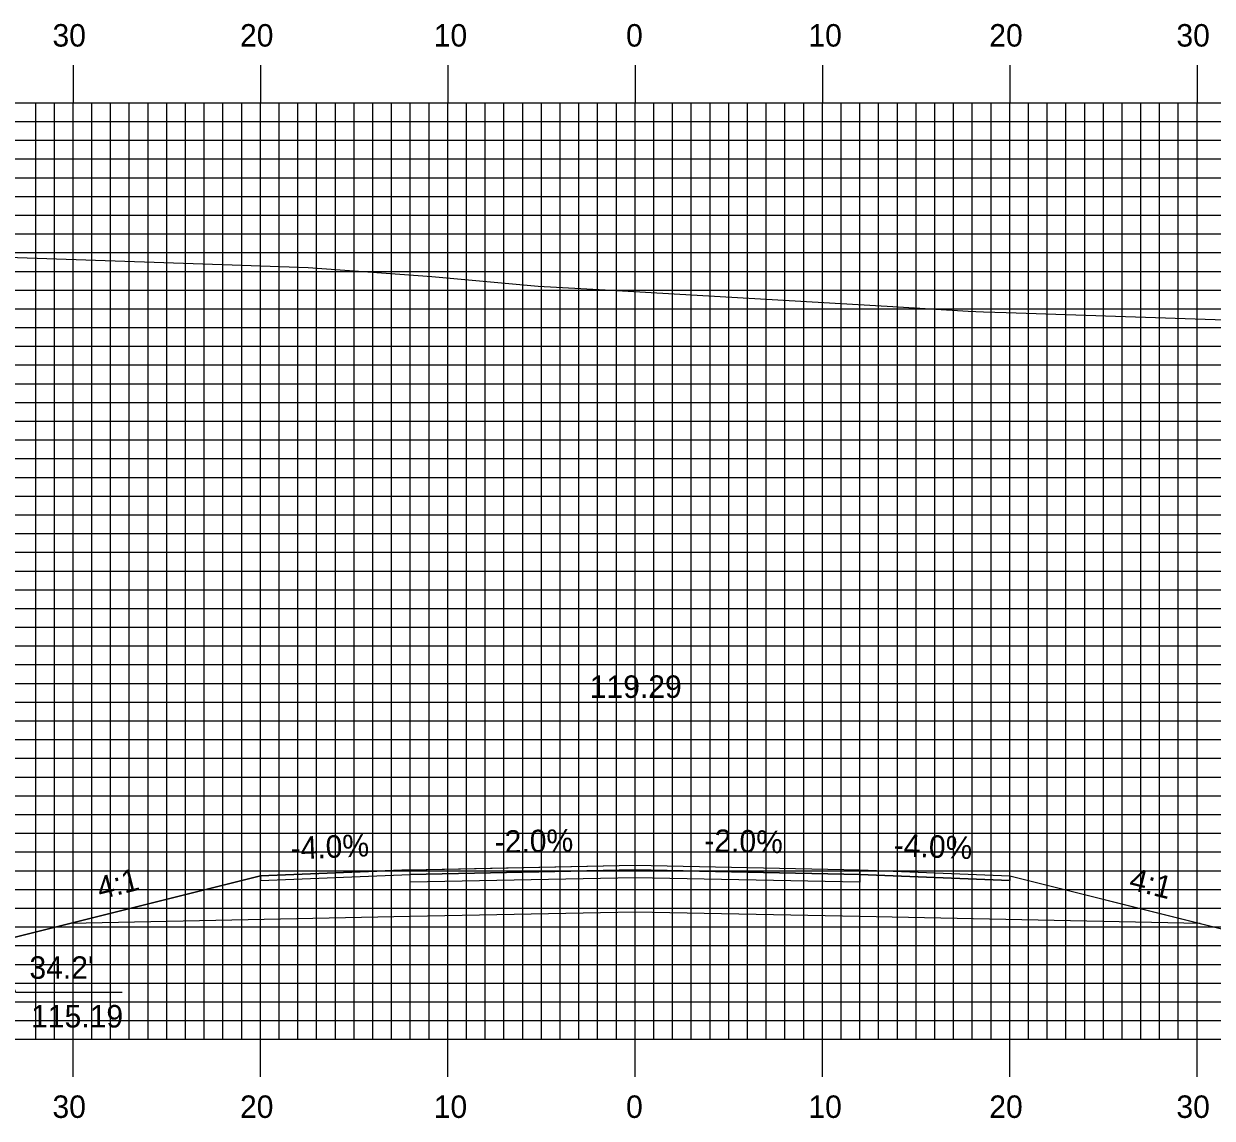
# Model space of a CAD drawing. Extents: x 1770055 to 1770398, y 442591 to 442811.
# Drawn here: x 1770187.9 to 1770251.3, y 442679.4 to 442737.9 of the extents above; entities that cross this region are included whole.
import ezdxf

# ---------------------------------------------------------------- set-up
doc = ezdxf.new("R2010")
doc.units = 0
for name, color, linetype in [('ANNOTATION', 7, 'Continuous'), ('D_Roadway_Centerline', 7, 'Continuous'), ('D_Roadway_Centerline_Text', 7, 'Continuous'), ('D_Roadway_Edge_Shoulder', 7, 'Continuous'), ('D_Roadway_Edge_TW', 7, 'Continuous'), ('D_Roadway_Pavement', 7, 'Continuous'), ('D_Roadway_SlopeLines', 7, 'Continuous'), ('D_Roadway_SubGrade', 7, 'Continuous'), ('H_V ANNOTATION', 7, 'Continuous'), ('MAJOR', 7, 'Continuous'), ('MINOR', 7, 'Continuous'), ('S_Roadway_Centerline', 7, 'Continuous')]:
    doc.layers.add(name, color=color, linetype=linetype)

msp = doc.modelspace()

# ---------------------------------------------------------------- linework, layer by layer
at = {"layer": 'ANNOTATION'}
msp.add_lwpolyline([(1770193.153, 442686.167), (1770187.461, 442686.167), (1770186.354, 442688.852)], dxfattribs=at)
at = {"layer": 'D_Roadway_Centerline'}
msp.add_lwpolyline([(1770126.762, 442726.961), (1770128.012, 442726.836), (1770129.262, 442726.509), (1770130.512, 442725.979), (1770131.761, 442725.247), (1770143.721, 442717.274), (1770186.354, 442688.852), (1770190.354, 442689.852), (1770200.525, 442692.396), (1770200.528, 442692.396), (1770208.529, 442692.716), (1770210.349, 442692.753), (1770220.528, 442692.956), (1770232.528, 442692.716), (1770240.528, 442692.396), (1770250.702, 442689.852), (1770254.136, 442688.994)], dxfattribs=at)
at = {"layer": 'D_Roadway_Edge_Shoulder'}
for points in [[(1770208.528, 442692.716), (1770200.528, 442692.396), (1770200.528, 442692.146), (1770208.528, 442692.466)], [(1770232.528, 442692.716), (1770240.528, 442692.396), (1770240.528, 442692.146), (1770232.528, 442692.466)]]:
    msp.add_lwpolyline(points, close=True, dxfattribs=at)
at = {"layer": 'D_Roadway_Edge_TW'}
msp.add_lwpolyline([(1770208.528, 442692.466), (1770208.528, 442692.716), (1770220.528, 442692.956), (1770232.528, 442692.716), (1770232.528, 442692.466), (1770220.528, 442692.706)], close=True, dxfattribs=at)
at = {"layer": 'D_Roadway_Pavement'}
msp.add_lwpolyline([(1770208.528, 442692.049), (1770208.528, 442692.466), (1770220.528, 442692.706), (1770232.528, 442692.466), (1770232.528, 442692.049), (1770220.528, 442692.289)], close=True, dxfattribs=at)
at = {"layer": 'D_Roadway_SlopeLines'}
for points in [[(1770200.528, 442692.396), (1770186.354, 442688.852)], [(1770240.528, 442692.396), (1770254.702, 442688.852)]]:
    msp.add_lwpolyline(points, dxfattribs=at)
at = {"layer": 'D_Roadway_SubGrade'}
msp.add_lwpolyline([(1770208.528, 442690.216), (1770190.354, 442689.852), (1770200.528, 442692.396), (1770200.528, 442692.146), (1770208.528, 442692.466), (1770220.528, 442692.706), (1770232.528, 442692.466), (1770240.528, 442692.146), (1770240.528, 442692.396), (1770250.702, 442689.852), (1770232.528, 442690.216), (1770220.528, 442690.456)], close=True, dxfattribs=at)
at = {"layer": 'MAJOR'}
for p, q in [((1770190.528, 442735.669), (1770190.528, 442733.665)), ((1770200.528, 442735.669), (1770200.528, 442733.665)), ((1770210.528, 442735.669), (1770210.528, 442733.665)), ((1770220.528, 442735.669), (1770220.528, 442733.665)), ((1770230.528, 442735.669), (1770230.528, 442733.665)), ((1770240.528, 442735.669), (1770240.528, 442733.665)), ((1770250.528, 442735.669), (1770250.528, 442733.665)), ((1770080.528, 442733.665), (1770360.528, 442733.665)), ((1770080.528, 442733.665), (1770360.528, 442733.665)), ((1770190.528, 442683.665), (1770190.528, 442733.665)), ((1770200.528, 442683.665), (1770200.528, 442733.665)), ((1770210.528, 442683.665), (1770210.528, 442733.665)), ((1770220.528, 442683.665), (1770220.528, 442733.665)), ((1770230.528, 442683.665), (1770230.528, 442733.665)), ((1770240.528, 442683.665), (1770240.528, 442733.665)), ((1770250.528, 442683.665), (1770250.528, 442733.665)), ((1770080.528, 442728.665), (1770360.528, 442728.665)), ((1770080.528, 442723.665), (1770360.528, 442723.665)), ((1770080.528, 442718.665), (1770360.528, 442718.665)), ((1770080.528, 442713.665), (1770360.528, 442713.665)), ((1770080.528, 442708.665), (1770360.528, 442708.665)), ((1770080.528, 442703.665), (1770360.528, 442703.665)), ((1770080.528, 442698.665), (1770360.528, 442698.665)), ((1770080.528, 442693.665), (1770360.528, 442693.665)), ((1770080.528, 442688.665), (1770360.528, 442688.665)), ((1770080.528, 442683.665), (1770360.528, 442683.665)), ((1770080.528, 442683.665), (1770360.528, 442683.665)), ((1770190.528, 442681.661), (1770190.528, 442683.665)), ((1770200.528, 442681.661), (1770200.528, 442683.665)), ((1770210.528, 442681.661), (1770210.528, 442683.665)), ((1770220.528, 442681.661), (1770220.528, 442683.665)), ((1770230.528, 442681.661), (1770230.528, 442683.665)), ((1770240.528, 442681.661), (1770240.528, 442683.665)), ((1770250.528, 442681.661), (1770250.528, 442683.665))]:
    msp.add_line(p, q, dxfattribs=at)
at = {"layer": 'MINOR'}
for p, q in [((1770188.528, 442683.665), (1770188.528, 442733.665)), ((1770189.528, 442683.665), (1770189.528, 442733.665)), ((1770191.528, 442683.665), (1770191.528, 442733.665)), ((1770192.528, 442683.665), (1770192.528, 442733.665)), ((1770193.528, 442683.665), (1770193.528, 442733.665)), ((1770194.528, 442683.665), (1770194.528, 442733.665)), ((1770195.528, 442683.665), (1770195.528, 442733.665)), ((1770196.528, 442683.665), (1770196.528, 442733.665)), ((1770197.528, 442683.665), (1770197.528, 442733.665)), ((1770198.528, 442683.665), (1770198.528, 442733.665)), ((1770199.528, 442683.665), (1770199.528, 442733.665)), ((1770201.528, 442683.665), (1770201.528, 442733.665)), ((1770202.528, 442683.665), (1770202.528, 442733.665)), ((1770203.528, 442683.665), (1770203.528, 442733.665)), ((1770204.528, 442683.665), (1770204.528, 442733.665)), ((1770205.528, 442683.665), (1770205.528, 442733.665)), ((1770206.528, 442683.665), (1770206.528, 442733.665)), ((1770207.528, 442683.665), (1770207.528, 442733.665)), ((1770208.528, 442683.665), (1770208.528, 442733.665)), ((1770209.528, 442683.665), (1770209.528, 442733.665)), ((1770211.528, 442683.665), (1770211.528, 442733.665)), ((1770212.528, 442683.665), (1770212.528, 442733.665)), ((1770213.528, 442683.665), (1770213.528, 442733.665)), ((1770214.528, 442683.665), (1770214.528, 442733.665)), ((1770215.528, 442683.665), (1770215.528, 442733.665)), ((1770216.528, 442683.665), (1770216.528, 442733.665)), ((1770217.528, 442683.665), (1770217.528, 442733.665)), ((1770218.528, 442683.665), (1770218.528, 442733.665)), ((1770219.528, 442683.665), (1770219.528, 442733.665)), ((1770221.528, 442683.665), (1770221.528, 442733.665)), ((1770222.528, 442683.665), (1770222.528, 442733.665)), ((1770223.528, 442683.665), (1770223.528, 442733.665)), ((1770224.528, 442683.665), (1770224.528, 442733.665)), ((1770225.528, 442683.665), (1770225.528, 442733.665)), ((1770226.528, 442683.665), (1770226.528, 442733.665)), ((1770227.528, 442683.665), (1770227.528, 442733.665)), ((1770228.528, 442683.665), (1770228.528, 442733.665)), ((1770229.528, 442683.665), (1770229.528, 442733.665)), ((1770231.528, 442683.665), (1770231.528, 442733.665)), ((1770232.528, 442683.665), (1770232.528, 442733.665)), ((1770233.528, 442683.665), (1770233.528, 442733.665)), ((1770234.528, 442683.665), (1770234.528, 442733.665)), ((1770235.528, 442683.665), (1770235.528, 442733.665)), ((1770236.528, 442683.665), (1770236.528, 442733.665)), ((1770237.528, 442683.665), (1770237.528, 442733.665)), ((1770238.528, 442683.665), (1770238.528, 442733.665)), ((1770239.528, 442683.665), (1770239.528, 442733.665)), ((1770241.528, 442683.665), (1770241.528, 442733.665)), ((1770242.528, 442683.665), (1770242.528, 442733.665)), ((1770243.528, 442683.665), (1770243.528, 442733.665)), ((1770244.528, 442683.665), (1770244.528, 442733.665)), ((1770245.528, 442683.665), (1770245.528, 442733.665)), ((1770246.528, 442683.665), (1770246.528, 442733.665)), ((1770247.528, 442683.665), (1770247.528, 442733.665)), ((1770248.528, 442683.665), (1770248.528, 442733.665)), ((1770249.528, 442683.665), (1770249.528, 442733.665)), ((1770080.528, 442732.665), (1770360.528, 442732.665)), ((1770080.528, 442731.665), (1770360.528, 442731.665)), ((1770080.528, 442730.665), (1770360.528, 442730.665)), ((1770080.528, 442729.665), (1770360.528, 442729.665)), ((1770080.528, 442727.665), (1770360.528, 442727.665)), ((1770080.528, 442726.665), (1770360.528, 442726.665)), ((1770080.528, 442725.665), (1770360.528, 442725.665)), ((1770080.528, 442724.665), (1770360.528, 442724.665)), ((1770080.528, 442722.665), (1770360.528, 442722.665)), ((1770080.528, 442721.665), (1770360.528, 442721.665)), ((1770080.528, 442720.665), (1770360.528, 442720.665)), ((1770080.528, 442719.665), (1770360.528, 442719.665)), ((1770080.528, 442717.665), (1770360.528, 442717.665)), ((1770080.528, 442716.665), (1770360.528, 442716.665)), ((1770080.528, 442715.665), (1770360.528, 442715.665)), ((1770080.528, 442714.665), (1770360.528, 442714.665)), ((1770080.528, 442712.665), (1770360.528, 442712.665)), ((1770080.528, 442711.665), (1770360.528, 442711.665)), ((1770080.528, 442710.665), (1770360.528, 442710.665)), ((1770080.528, 442709.665), (1770360.528, 442709.665)), ((1770080.528, 442707.665), (1770360.528, 442707.665)), ((1770080.528, 442706.665), (1770360.528, 442706.665)), ((1770080.528, 442705.665), (1770360.528, 442705.665)), ((1770080.528, 442704.665), (1770360.528, 442704.665)), ((1770080.528, 442702.665), (1770360.528, 442702.665)), ((1770080.528, 442701.665), (1770360.528, 442701.665)), ((1770080.528, 442700.665), (1770360.528, 442700.665)), ((1770080.528, 442699.665), (1770360.528, 442699.665)), ((1770080.528, 442697.665), (1770360.528, 442697.665)), ((1770080.528, 442696.665), (1770360.528, 442696.665)), ((1770080.528, 442695.665), (1770360.528, 442695.665)), ((1770080.528, 442694.665), (1770360.528, 442694.665)), ((1770080.528, 442692.665), (1770360.528, 442692.665)), ((1770080.528, 442691.665), (1770360.528, 442691.665)), ((1770080.528, 442690.665), (1770360.528, 442690.665)), ((1770080.528, 442689.665), (1770360.528, 442689.665)), ((1770080.528, 442687.665), (1770360.528, 442687.665)), ((1770080.528, 442686.665), (1770360.528, 442686.665)), ((1770080.528, 442685.665), (1770360.528, 442685.665)), ((1770080.528, 442684.665), (1770360.528, 442684.665))]:
    msp.add_line(p, q, dxfattribs=at)
at = {"layer": 'S_Roadway_Centerline'}
msp.add_lwpolyline([(1770121.048, 442727.056), (1770126.39, 442726.968), (1770141.191, 442726.69), (1770144.283, 442726.671), (1770149.24, 442726.636), (1770160.165, 442726.44), (1770179.315, 442725.697), (1770179.585, 442725.683), (1770179.724, 442725.676), (1770199.014, 442725.017), (1770203.08, 442724.873), (1770209.671, 442724.387), (1770215.35, 442723.878), (1770218.936, 442723.678), (1770234.279, 442722.779), (1770238.306, 442722.542), (1770239.134, 442722.503), (1770240.342, 442722.476), (1770257.862, 442721.875)], dxfattribs=at)

# ---------------------------------------------------------------- texts
at = {"layer": 'ANNOTATION'}
for s, rotation, p in [('-4.0%', 2.29048, (1770202.16, 442693.263)), ('-2.0%', 1.14581, (1770213.045, 442693.607)), ('-2.0%', 358.85425, (1770224.214, 442693.683)), ('-4.0%', 357.70928, (1770234.32, 442693.446)), ('4:1', 14.03803, (1770191.975, 442691.119)), ('4:1', 345.96196, (1770246.838, 442691.68))]:
    msp.add_text(s, height=1.2, rotation=rotation, dxfattribs=at).set_placement(p)
for s, p in [("34.2'", (1770188.196, 442686.893)), ('115.19', (1770188.287, 442684.293))]:
    msp.add_text(s, height=1.2, dxfattribs=at).set_placement(p)
at = {"layer": 'D_Roadway_Centerline'}
for s, p in [('C', (1770220.523, 442692.956)), ('L', (1770220.528, 442692.949))]:
    msp.add_text(s, height=0.0146, dxfattribs=at).set_placement(p)
at = {"layer": 'D_Roadway_Centerline_Text'}
msp.add_text('119.29', height=1.2, dxfattribs=at).set_placement((1770218.11, 442701.891))
at = {"layer": 'H_V ANNOTATION'}
for s, p in [('30', (1770189.425, 442736.665)), ('20', (1770199.436, 442736.665)), ('10', (1770209.779, 442736.665)), ('0', (1770220.046, 442736.665)), ('10', (1770229.779, 442736.665)), ('20', (1770239.436, 442736.665)), ('30', (1770249.425, 442736.665)), ('30', (1770189.425, 442679.465)), ('20', (1770199.436, 442679.465)), ('10', (1770209.779, 442679.465)), ('0', (1770220.046, 442679.465)), ('10', (1770229.779, 442679.465)), ('20', (1770239.436, 442679.465)), ('30', (1770249.425, 442679.465))]:
    msp.add_text(s, height=1.2, dxfattribs=at).set_placement(p)

doc.saveas('drawing.dxf')
